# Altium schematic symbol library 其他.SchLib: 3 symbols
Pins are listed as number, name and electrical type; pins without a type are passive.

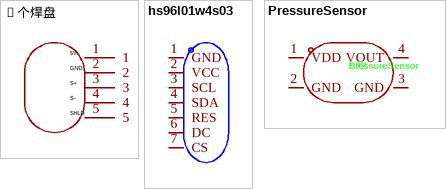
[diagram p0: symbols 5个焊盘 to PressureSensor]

## 5个焊盘
designator U??  (value not drawn)
Convert to PCB: yes
pins: 1, 2, 3, 4, 5

## hs96l01w4s03
designator OLED??  (value not drawn)
接口类型:SPI;尺寸(inch):0.96;像素分辨率:128x64;; Manufacturer: HS(汉昇); AddInBom: yes; ModelId: 7927fe0e3c8842749d8ccfcaf6d2f492; ModelName: OLED-TH_HS96L01W4S03; ModelTransform: 1074.801,1094.486,0,0,0,0,0,-488.188,-157.48; Interface: SPI; Dot Pixels: 128x64; Type of Drive: 无源(PMOLED); Display Range: 21.74x10.86mm; Display Color: 白色; Luminance: 100cd/m2; Quiescent Current: 5uA; Voltage - Supply  For Logic: 1.65V~3.3V
footprint OLED-TH_HS96L01W4S03
pins: 1 GND, 2 VCC, 3 SCL, 4 SDA, 5 RES, 6 DC, 7 CS

## PressureSensor
designator S??
模拟压力传感器; Manufacturer Part: MAX40200AUK+T; Add into BOM: yes
footprint PressureSensor
pins: 1 VDD, 2 GND, 3 GND, 4 VOUT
